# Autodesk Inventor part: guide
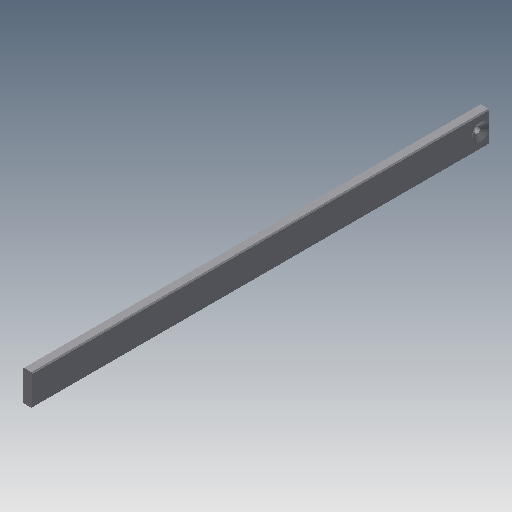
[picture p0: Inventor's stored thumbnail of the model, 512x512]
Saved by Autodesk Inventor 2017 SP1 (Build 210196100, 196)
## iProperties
Shininess: 64.0
Length Units: 11269
Angle Units: 11279
Time Units: 11290
Mass Units: 11283
Length Display Precision: 3
Angle Display Precision: 2
Compacted: True
Part Number: guide
Document SubType Name: Modeling
Created: 2003-07
Material: Générique
Designer: trameau
Density: 1 g/cm^3
Appearance: Par défaut
Density: 0.0
Volumn: 0.0
Area: 0.0
PropertySet Name: Model Information
Control State: 0
Master: False
Checked Out: False
Author: trameau
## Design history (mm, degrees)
sketch "Esquisse1"
  geometry: L1 (-4.172, 0.655)-(0.328, 0.655); L2 (0.328, 0.655)-(0.328, -13.845); L3 (0.328, -13.845)-(-4.172, -13.845); L4 (-4.172, -13.845)-(-4.172, 0.655)
  constraints: 8 end point, 2 parallel, 1 horizontal, 1 perpendicular
  dimensions: "d0" = 4.5 distance between parallel lines of L2 L4; "d1" = 14.5 distance between parallel lines of L1 L3
extrude "Extrusion1" new body sketch "Esquisse1" distance "d2" = 215; taper "d3" = 0 deg
chamfer "Chanfrein1" distance "d4" = 0.5; stored, may be unused: second distance "d5" = 2, angle "d6" = 45 deg
hole "Perçage2" diameter "d18" = 3; stored, may be unused: countersink angle "d22" = 90 deg, drill point angle "d24" = 118 deg; dims "d16" = 7.25, "d17" = 4, "d19" = 6, "d20" = 4, "d21" = 2, "d23" = 8
chamfer "Chanfrein2" distance "d25" = 1.5; stored, may be unused: second distance "d26" = 2, angle "d27" = 60 deg
node "Solide1"
node "Corps solides"
node "Corps surfaciques"
